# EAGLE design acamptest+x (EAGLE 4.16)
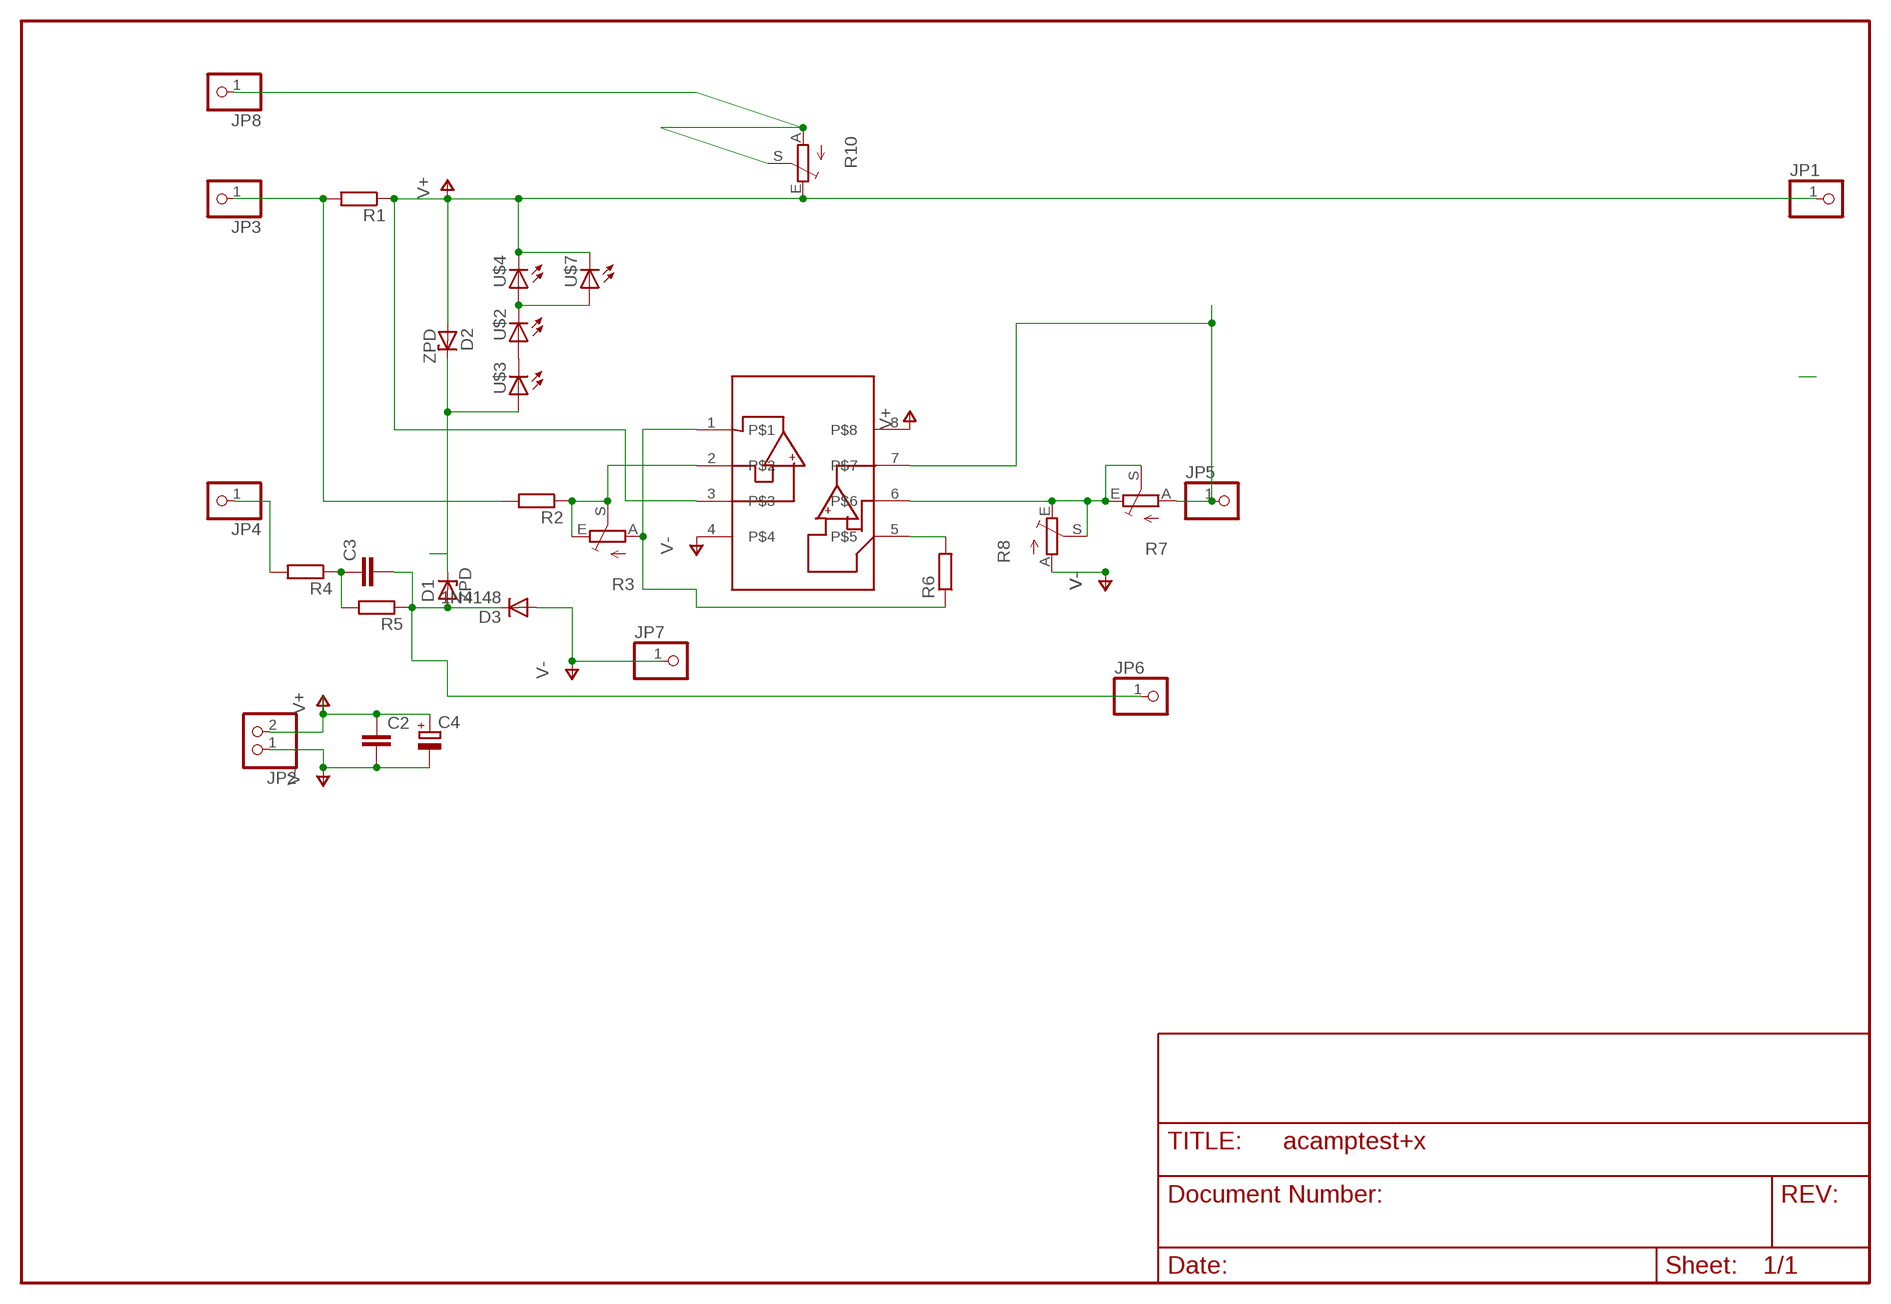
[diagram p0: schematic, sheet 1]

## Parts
C2  C-EU050-024X044  [C050-024X044]
C3  C-EU075-042X103  [C075-042X103]
C4  CPOL-EUE2-5  [E2-5]
D1  ZPD  [DO35Z10]
D2  ZPD  [DO35Z10]
D3  1N4148  [DO35-10]
JP1  PINHD-1X1  [1X01]
JP2  PINHD-1X2  [1X02]
JP3  PINHD-1X1  [1X01]
JP4  PINHD-1X1  [1X01]
JP5  PINHD-1X1  [1X01]
JP6  PINHD-1X1  [1X01]
JP7  PINHD-1X1  [1X01]
JP8  PINHD-1X1  [1X01]
R1  R-EU_0207/15  [0207/15]
R2  R-EU_0207/15  [0207/15]
R3  TRIM_EU-LI15  [LI15]
R4  R-EU_0207/15  [0207/15]
R5  R-EU_0207/15  [0207/15]
R6  R-EU_0207/15  [0207/15]
R7  TRIM_EU-LI15  [LI15]
R8  TRIM_EU-LI15  [LI15]
R10  TRIM_EU-LI15  [LI15]
U$1  MCP6042SOIC  [SO-08]
U$2  LEDCHIPLED_0805  [CHIPLED_0805]
U$3  LEDCHIPLED_0805  [CHIPLED_0805]
U$4  LEDCHIPLED_0805  [CHIPLED_0805]
U$7  LEDP-LCC-4  [P-LCC-4]

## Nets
AC(N): JP3.1 R1.2 R2.2
N$1: JP5.1 R7.A U$1.7
N$2: R7.E R7.S R8.E R8.S U$1.6
N$3: R3.A R6.1 U$1.1
N$5: R6.2 U$1.5
N$6: U$2.A U$3.C
N$7: U$2.C U$4.A U$7.A
N$8: D1.C D2.C U$3.A
N$9: JP8.1 R10.A R10.S
N$12: C3.1 R4.1 R5.2
N$13: JP4.1 R4.2
N$14: C3.2 D1.A D3.C JP6.1 R5.1
N$16: R2.1 R3.E R3.S U$1.2
V+: C2.1 C4.+ D2.A JP1.1 JP2.2 R1.1 R10.E U$1.3 U$1.8 U$4.C U$7.C@4(C)
V-: C2.2 C4.- D3.A JP2.1 JP7.1 R8.A U$1.4

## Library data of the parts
C2 = rcl:C-EU: CAPACITOR, European symbol
C3 = rcl-2:C-EU: CAPACITOR, European symbol
C4 = rcl-2:CPOL-EU: POLARIZED CAPACITOR, European symbol
D1 D2 = diode:ZPD: Z DIODE
D3 = diode-1:1N4148: DIODE
JP1 JP3-JP8 = pinhead(2):PINHD-1X1: PIN HEADER
JP2 = pinhead:PINHD-1X2: PIN HEADER
R1 R2 R4-R6 = rcl:R-EU_: RESISTOR, European symbol
R3 R7 R8 R10 = pot:TRIM_EU-: POTENTIOMETER
U$1 = microchip-3:MCP6042
U$2-U$4 U$7 = led(3):LED: LED

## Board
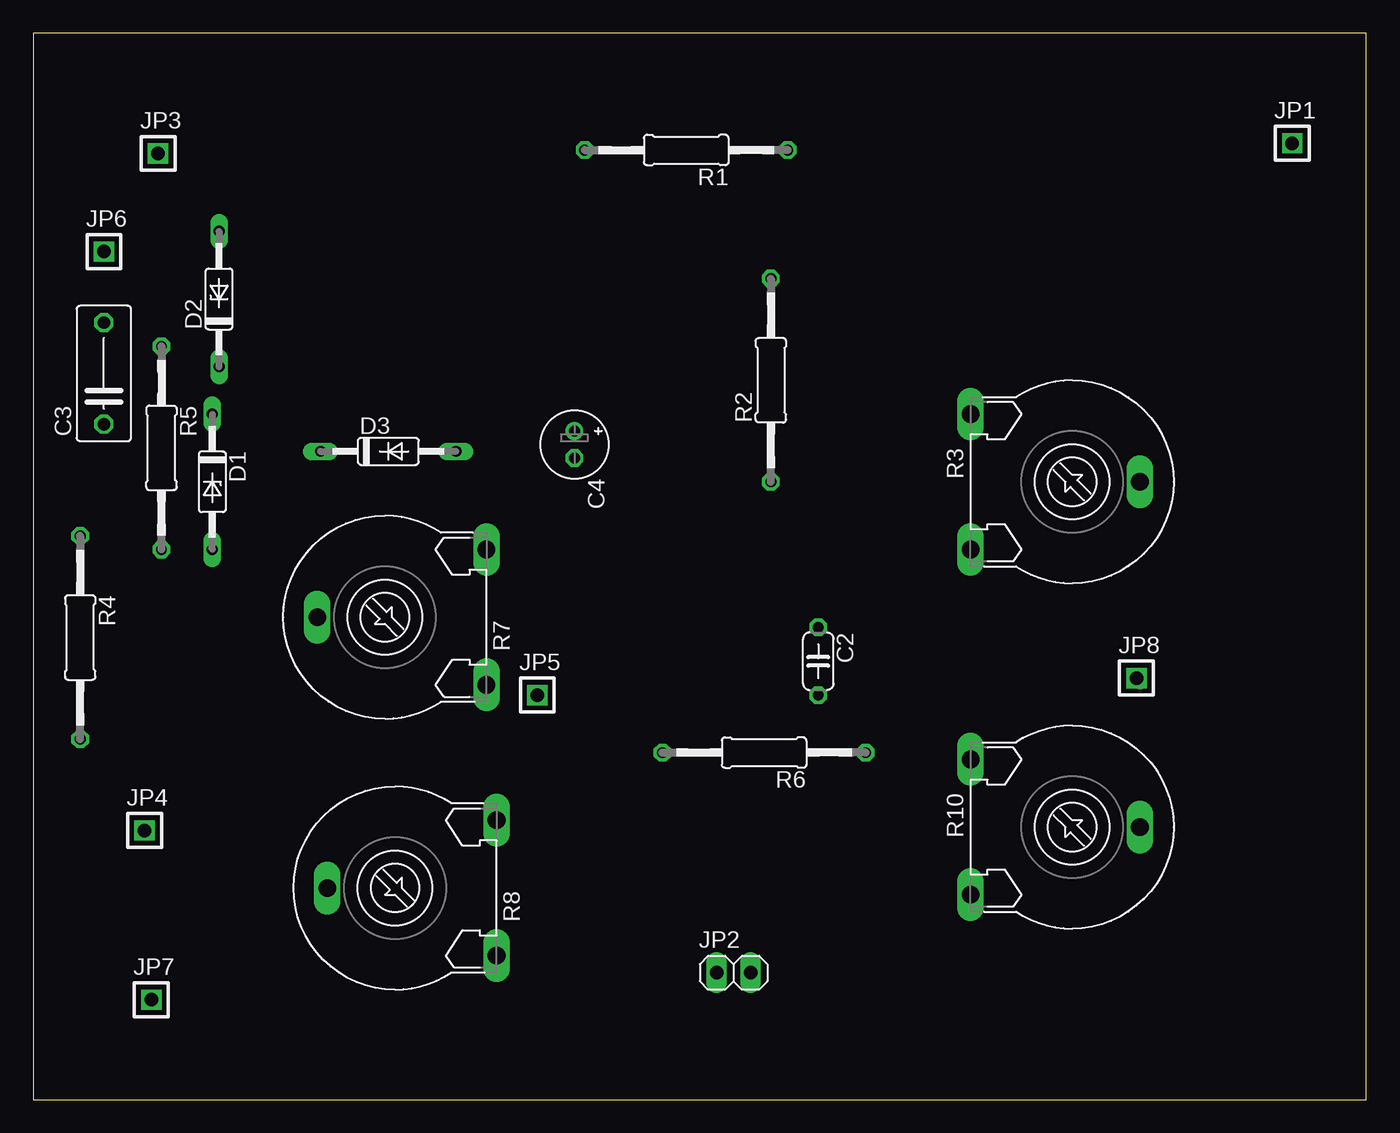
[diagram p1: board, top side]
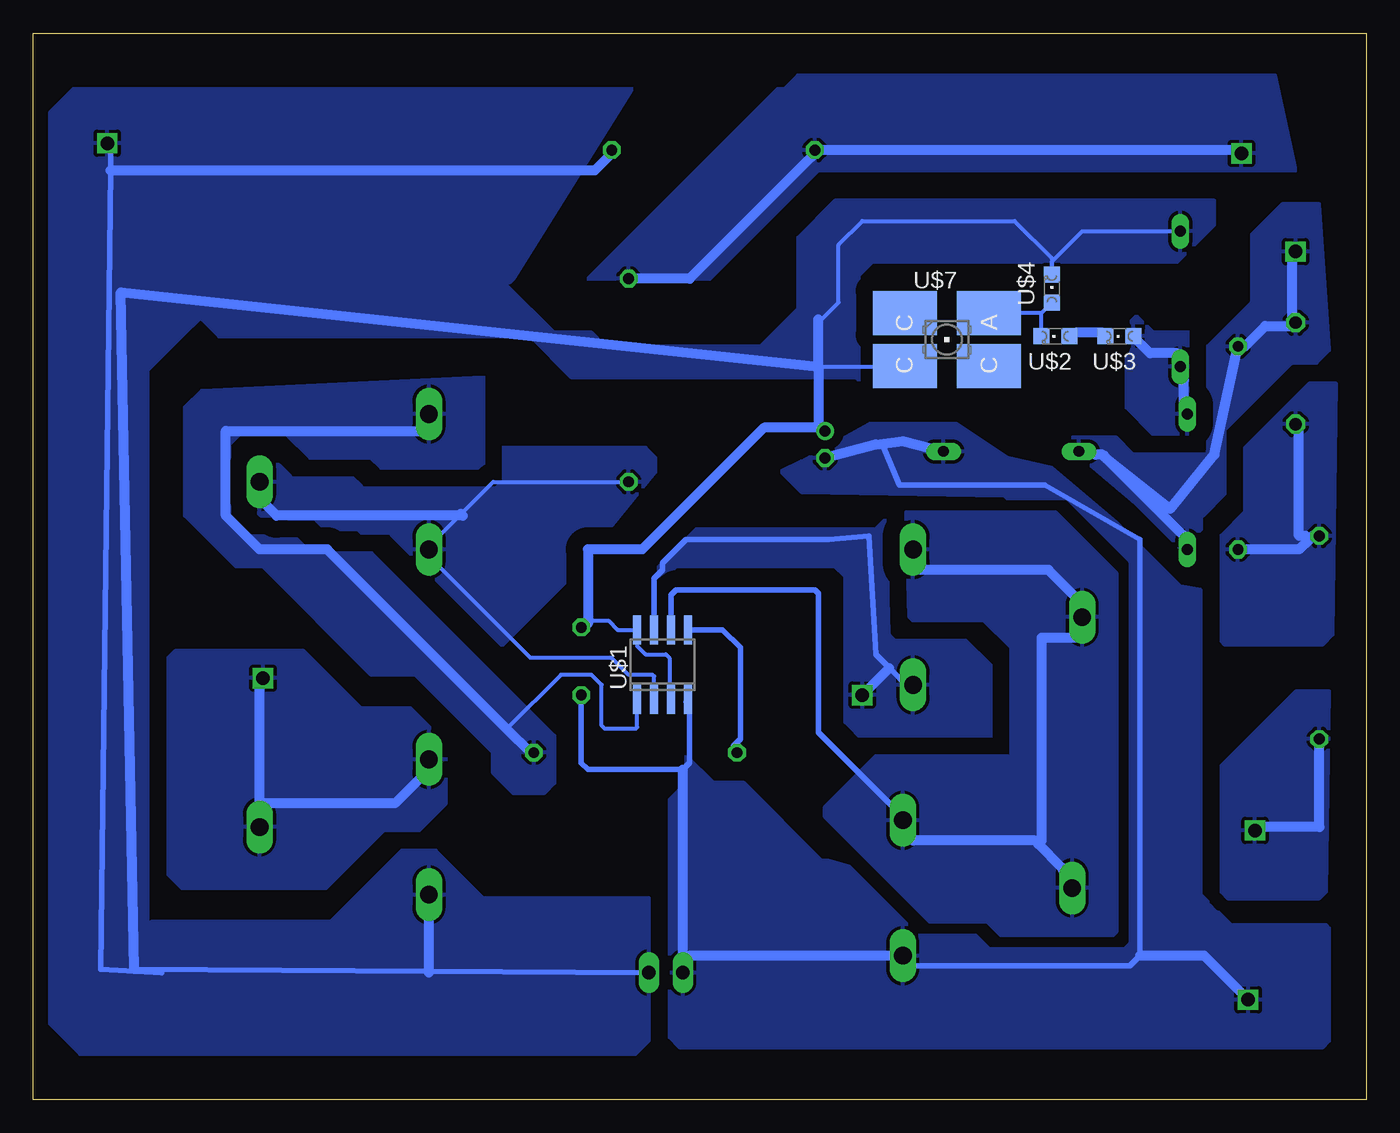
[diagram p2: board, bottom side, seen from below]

Size 100 x 80 mm. Coordinates in mm from the lower left corner, seen from the top.
Outline: 0,0 100,0 100,80 0,80 0,0
Copper layers (1*16): Top 0.035mm / dielectric 1.5mm / Bottom 0.035mm
Design rules "default": minimum track width 30mil, minimum drill 24mil, track to track 30mil, track to pad 30mil, pad to pad 8mil, via to via 8mil, smd to smd 8mil, copper to edge 40mil, drill to drill 20mil, minimum pad ring 10mil, minimum via ring 8mil, stop-mask expansion 4mil, vias tented up to drill 0mil, thermal gap 10mil

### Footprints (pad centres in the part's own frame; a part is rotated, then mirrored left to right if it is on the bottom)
C050-024X044 = drill 0.813 octagon: 1 -2.54,0; 2 2.54,0
C075-042X103 = drill 0.914 octagon: 1 -3.81,0; 2 3.81,0
E2-5 = drill 0.813 pad 1.27 round: + -1.016,0 | drill 0.813 pad 1.27 octagon: - 1.016,0
DO35Z10 = drill 0.813 long: A 5.08,0; C -5.08,0
DO35-10 = drill 0.813 long: A 5.08,0; C -5.08,0
1X01 = drill 1.016 square: 1 0,0
1X02 = drill 1.016 long: 1 -1.27,0; 2 1.27,0
0207/15 = drill 0.813 octagon: 1 -7.62,0; 2 7.62,0
LI15 = drill 1.321 long: A -5.08,-7.62; E 5.08,-7.62; S 0,5.08
SO-08 = smd 0.6 x 2.2: 1 -1.905,-2.6; 2 -0.635,-2.6; 3 0.635,-2.6; 4 1.905,-2.6; 5 1.905,2.6; 6 0.635,2.6; 7 -0.635,2.6; 8 -1.905,2.6
CHIPLED_0805 = smd 1.2 x 1.2: A 0,-1.05; C 0,1.05
P-LCC-4 = smd 3.3 x 4.8: A -2,3.15; C@1 -2,-3.15; C@3 2,3.15; C@4 2,-3.15

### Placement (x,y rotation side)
C2  58.89,32.89 270 top
C3  5.3,54.48 90 top
C4  40.6,49.14 270 top
D1  13.42,46.35 270 top
D2  13.93,60.07 90 top
D3  26.63,48.64 0 top
JP1  94.45,71.75 0 top
JP2  52.54,9.52 0 top
JP3  9.36,70.99 0 top
JP4  8.34,20.19 0 top
JP5  37.81,30.35 0 top
JP6  5.3,63.62 0 top
JP7  8.85,7.49 0 top
JP8  82.77,31.62 0 top
R1  48.98,71.24 180 top
R2  55.33,53.97 90 top
R3  77.94,46.35 270 top
R4  3.52,34.67 270 top
R5  9.61,48.89 270 top
R6  54.83,26.03 180 top
R7  26.38,36.19 90 top
R8  27.14,15.87 90 top
R10  77.94,20.44 270 top
U$1  52.79,32.63 0 bottom
U$2  23.33,57.27 90 bottom
U$3  18.5,57.27 90 bottom
U$4  23.58,60.83 0 bottom
U$7  31.46,57.02 270 bottom

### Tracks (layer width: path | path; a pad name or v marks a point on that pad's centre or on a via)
AC(N)
  Bottom 0.762: R2.2 50.76,61.59 41.62,70.73 R1.2 9.61,71.24 JP3.1
  pour Bottom: 6.82,76.83 42.63,76.83 43.65,75.81 44.16,75.81 58.38,61.59 49.24,61.59 41.11,69.72 5.3,69.72
N$1
  Bottom 0.406: U$1.7 53.43,39.11 52.79,39.75 52.79,40.25 51.02,42.03 40.35,42.03 37.3,42.29 36.79,33.4 35.78,32.38 34.25,30.86 R7.A
  Bottom 0.762: 35.78,32.38 JP5.1
  pour Bottom (isolate 1.27, rank 3): 29.68,35.43 29.17,35.43 27.65,33.9 27.65,26.79 37.55,26.79 39.08,28.32 39.08,39.24 39.84,40 51.78,40 53.05,38.73 53.05,40.51 50.76,42.79 36.79,42.79 36.03,43.56
N$2
  Bottom 0.406: U$1.6 52.16,37.84 51.78,38.22 41.36,38.22 41.11,37.97 41.11,27.55 34.51,20.95 R8.E
  Bottom 0.762: 24.6,19.17 24.85,19.43 34,19.43 R8.E | 24.6,19.17 22.82,17.39 R8.S | R7.E 33.49,39.75 23.84,39.75 21.81,37.71 R7.S 21.81,34.67 24.35,34.67 24.35,19.43 24.6,19.17
  pour Bottom: 34.51,44.06 23.33,44.06 18.76,39.49 18.76,12.57 19.01,12.31 27.39,12.31 28.41,13.33 32.73,13.33 40.6,21.2 40.6,21.97 36.79,25.78 26.89,25.78 26.63,25.52 26.63,33.9 28.66,35.94 34,35.94 34.25,36.19
N$3
  Bottom 0.305: U$1.1 54.7,27.93 54.83,27.81 57.11,27.81 57.37,28.06 57.37,31.11 58.13,31.87 60.41,31.87 64.48,27.81
  Bottom 0.762: R6.1 62.7,26.03 64.48,27.81 77.94,41.27 83.02,41.27 85.56,43.81 85.56,50.16 70.32,50.16 R3.A
  pour Bottom (isolate 1.27): 66.26,54.22 66.26,47.62 66,47.37 73.88,47.37 74.64,48.13 79.21,48.13 80.99,49.91 84.54,49.91 85.31,49.14 85.31,43.3 84.29,42.29 80.48,42.29 79.21,41.02 74.64,41.02 60.92,27.3 60.92,23.74 61.68,22.98 63.97,22.98 65.49,24.51 65.49,26.03 71.34,31.87 74.64,31.87 82.77,40 84.8,40 88.61,43.81 88.61,51.94 87.34,53.21
N$5
  Bottom 0.406: U$1.5 48.28,35.23 46.95,33.9 46.95,27.05 47.46,26.54 47.46,26.03 47.21,25.78 R6.2
N$6
  Bottom 0.762: U$3.C 19.77,57.53 21.81,57.53 U$2.A
N$7
  Bottom 0.305: U$4.A 23.62,59.78 24.38,59.02 | U$2.C 24.38,59.02 | U$7.A 27.93,59.02 27.9,59.05 27.87,59.02 24.38,59.02
N$8
  Bottom 0.762: U$3.A 17.23,57.02 16.22,56 14.19,56 D2.C 13.68,53.97 13.68,52.45 D1.C
  pour Bottom (isolate 1.27, rank 4): 12.66,57.53 15.96,57.53 17.23,58.8 18,58.03 18,51.94 15.96,49.91 12.66,49.91
N$9
  Top 0.762: JP8.1 83.02,31.11
  Bottom 0.762: 83.02,22.22 72.86,22.22 70.32,24.76 R10.A | 83.02,22.22 83.02,31.11 JP8.1 | 83.02,22.22 R10.S
  pour Bottom (isolate 1.27, rank 3): 69.05,29.33 75.4,29.33 79.72,33.65 89.37,33.65 89.88,33.14 89.88,16.89 88.86,15.87 77.69,15.87 77.43,16.12 75.15,16.12 69.05,22.22
N$12
  Bottom 0.762: 4.28,42.03 5.04,41.27 R5.2 | 4.28,42.03 4.03,42.29 R4.1 | C3.1 5.04,50.41 5.04,42.29 4.53,42.29 4.28,42.03
  pour Bottom (isolate 1.27, rank 2): 2.25,53.72 4.28,53.72 9.11,48.89 9.11,44.06 10.88,42.29 10.88,34.41 10.63,34.16 3.26,34.16 2.5,34.92
N$13
  Bottom 0.762: R4.2 3.52,20.44 8.09,20.44 JP4.1
  pour Bottom: 2.76,30.6 5.3,30.6 10.88,25.01 10.88,15.62 10.38,15.11 3.52,15.11 3.01,15.62
N$14
  Bottom 0.762: JP6.1 5.55,63.11 5.55,58.54 C3.2 5.55,58.03 7.58,58.03 9.11,56.51 R5.1 11.39,48.38 14.69,44.32 19.52,48.13 | 19.52,48.13 19.77,48.38 20.28,48.38 D3.C | 19.52,48.13 13.68,42.29 D1.A
  pour Bottom (isolate 1.27, rank 3): 3.52,67.18 6.31,67.18 8.6,64.89 8.6,59.81 11.9,56.51 11.9,48.64 11.65,48.38 17.49,48.38 18.76,49.65 22.06,49.65 23.33,48.38 23.08,48.38 13.17,38.48 13.17,42.03 9.36,45.84 9.36,50.16 5.04,54.48 4.53,54.48 2.76,56.26
N$16
  Bottom 0.305: U$1.2 53.43,31.74 53.56,31.87 55.33,31.87 56.6,33.14 62.7,33.14 70.57,41.02 R3.E 70.57,41.27 67.91,43.94 65.49,46.35 R2.1
  Bottom 0.762: R3.S 83.02,45.08 81.75,43.81 67.78,43.81 67.91,43.94
  pour Bottom (isolate 1.27, rank 4): 53.3,47.11 53.3,48.13 54.06,48.89 67.27,48.89 68.54,47.62 83.53,47.62 84.04,47.11 84.04,44.32 82.51,42.79 75.65,42.79 72.35,39.49 71.34,39.49 65.24,33.4 65.24,33.65 59.91,38.98
V+
  Bottom 0.305: C2.1 58.64,35.43 58.13,35.94 56.86,35.94 56.16,35.23 U$1.8 54.7,34.03 54.06,33.4 52.54,33.4 52.29,33.14 52.29,30.86 52.03,30.6 52.03,30.09 52.09,30.03 U$1.3 | D2.A 21.3,65.15 23.58,62.86 U$4.C 23.58,63.11 26.38,65.91 37.81,65.91 39.59,64.13 39.59,59.81 41.11,58.29 | U$7.C@4 34.54,55.02 34.51,54.99 41.11,54.99
  Bottom 0.406: JP2.2 70.32,9.63 92.42,9.77 90.39,9.52 94.96,9.77 94.2,69.72 94.2,71.24 94.7,71.75
  Bottom 0.762: R1.1 56.86,70.73 57.87,69.72 94.2,69.72 | 41.11,54.99 41.11,58.29 41.11,58.54 | 41.11,54.99 41.11,50.41 | 41.11,50.41 45.17,50.41 54.32,41.27 58.38,41.27 58.38,35.68 C2.1 | 41.11,50.41 C4.+ | 41.11,54.99 93.43,60.57 92.42,9.77 | 94.2,71.24 JP1.1 | R10.E 70.32,9.52 70.32,9.63
  pour Bottom: 55.08,75.81 96.99,75.81 98.77,74.04 98.77,5.71 96.48,3.42 54.83,3.42 53.81,4.44 53.81,15.11 66.26,15.11 69.81,18.66 72.35,18.66 77.69,13.33 91.15,13.33 91.4,13.08 91.4,54.73 84.8,61.34 64.22,61.34 63.97,61.59
  pour Bottom (isolate 1.27, rank 4): 11.39,67.43 39.84,67.43 42.63,64.64 42.63,59.3 45.43,56.51 57.11,56.51 58.13,57.53 60.92,57.53 64.48,61.08 87.08,61.08 87.34,60.83 87.34,58.54 86.07,57.27 62.7,57.27 59.65,54.22 38.32,54.22 38.06,53.97 38.06,61.84 37.05,62.86 14.19,62.86 11.39,65.65
V-
  Bottom 0.406: C2.2 58.89,25.27 58.38,24.76 51.27,24.76 50.76,25.27 50.76,29.59 51.02,29.84 50.89,29.97 U$1.4 | 36.79,49.14 36.28,49.14 35.01,46.1 24.09,46.1 16.98,42.03 16.98,10.79 17.74,10.03 34.51,10.03 35.01,10.54 R8.A
  Bottom 0.762: D3.A 34.76,49.4 36.79,49.14 C4.- | 51.27,24.76 JP2.1 50.76,10.79 R8.A | JP7.1 12.15,10.79 16.98,10.79
  pour Bottom (rank 2): 40.35,17.9 40.86,17.9 46.7,23.74 48.98,23.74 51.02,25.78 51.02,23.74 52.29,22.47 52.29,4.69 51.52,3.93 3.26,3.93 2.76,4.44 2.76,12.82 3.01,13.08 10.12,13.08 12.41,15.36 12.41,38.22 13.93,38.48 18.76,43.3 23.58,47.37 26.89,48.13 30.7,50.67 37.3,50.67 42.38,47.87 43.9,47.11 42.38,45.59 27.14,45.33 26.63,44.83 23.08,44.83 18.25,40 18.25,12.31 18.76,11.81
